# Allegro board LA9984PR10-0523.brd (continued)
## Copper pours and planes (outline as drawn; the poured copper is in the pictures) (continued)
GND on GND1: outline of 173 points within 0.25,0.25 237.15,192.85
GND on GND2: outline of 289 points within 0.26,0.26 237.14,192.84
GNDA on VCC (solid shape): outline of 1322 points within 1.02,7.52 43.27,31.94
GNDA on GND2 (solid shape): outline of 1489 points within 0.26,6.76 43.27,31.94
GNDA on GND1: 0.25,6.75 0.25,10.59 12.58,10.59 12.58,18.93 0.25,18.93 0.25,21.13 11.12,21.13 13.05,23.06 13.05,25.98 13.79,26.72 19.63,26.72 20.84,27.93 21.91,27.93 22.88,28.9 29.28,28.9 29.79,29.4 32.39,29.4 33.09,30.1 34.23,30.1 36.08,31.94 43.27,31.94 43.27,27.69 41.83,27.69 41.52,27.37 37.01,27.37 36.8,27.16 36.8,23.92 36.75,23.88 32.69,23.88 32.22,23.41 32.22,21.42 32.69,20.96 37.22,20.96 37.62,21.36 37.62,22.31 37.66,22.35 38.32,22.35 38.32,20.55 37.43,19.67 37.43,17.68 38.34,16.77 39.36,16.77 39.59,16.53 39.59,14.84 39.48,14.73 21.07,14.73 18.57,12.24 18.57,9.88 17.84,9.45 17.55,8.65 17.55,6.75
VCC on TOP (solid shape): 166.72,170.49 166.72,170.36 166.65,170.3 166.21,170.3 165.38,169.47 165.38,167.18 165.26,167.06 163.73,167.06 163.6,167.18 163.6,169.53 163.67,169.6 164.81,169.6 165.83,170.61 166.59,170.61
VIN on TOP (solid shape): 132.23,178.24 132.74,178.24 134.33,176.66 134.33,176.14 137.38,173.09 139.45,173.09 139.64,172.9 139.64,170.59 139.22,170.17 137.44,170.17 136.81,170.8 136.81,172.58 136.36,173.03 134.9,173.03 133.95,172.07 133.95,170.82 133.44,170.31 131.73,170.31 131.65,170.4 131.65,170.85 131.75,170.95 132.66,170.95 133.07,171.36 133.07,175.98 132.24,176.82 130.52,176.82 130.43,176.91 130.43,178.82 130.15,179.1 129.52,179.1 129.47,179.16 129.47,179.78 129.51,179.83 130.65,179.83
VIN on BOTTOM (solid shape): 142.33,173.03 142.33,172.2 142.71,171.82 143.54,171.82 143.86,171.5 143.86,170.74 143.6,170.49 142.52,170.49 141.7,169.66 139.09,169.66 138.9,169.85 138.9,172.65 139.79,173.53 141.82,173.53
+CHGRTC on BOTTOM (solid shape): 113.69,14.8 113.69,13.53 113.57,13.4 112.68,13.4 111.79,14.29 111.79,14.93 111.98,15.12 113.38,15.12
+CPU_CORE on TOP (solid shape): outline of 2868 points within 93.43,112.83 116.08,145.68
+CPU_CORE on BOTTOM (solid shape): outline of 751 points within 94.14,133.15 113.88,144.83
+CPU_CORE on BOTTOM (solid shape): outline of 1928 points within 94.62,112.68 117.56,125.72
+CPU_CORE on IN1 (solid shape): outline of 295 points within 95.02,115.37 115.85,123.76
+CPU_CORE on IN1 (solid shape): outline of 535 points within 94.01,137.47 111.47,145.02
+CPU_CORE on IN2 (solid shape): outline of 3879 points within 90.52,113.4 115.99,145.34
+CPU_CORE on IN3 (solid shape): outline of 4456 points within 90.52,113.4 115.99,145.34
+CPU_CORE on VCC: outline of 298 points within 88.36,112.13 116.42,144.97
+DIMM1_VREF_DQ on TOP (solid shape): 42.69,76.98 42.69,74.5 42.55,74.37 40.86,74.37 40.42,74.81 40.42,75.63 41.82,77.03 42.64,77.03
+DIMM1_VREF_DQ on BOTTOM (solid shape): 42,75.59 42,72.42 41.94,72.35 40.29,72.35 40.22,72.42 40.22,75.72 40.35,75.85 41.75,75.85
+DIMM2_VREF_DQ on TOP (solid shape): 120.71,75.78 120.71,72.41 120.42,72.12 119.03,72.12 118.65,72.51 118.65,75.68 118.84,75.87 120.62,75.87
+DIMM2_VREF_DQ on BOTTOM (solid shape): 120.55,75.55 120.55,72.38 120.49,72.32 118.84,72.32 118.77,72.38 118.77,75.68 118.9,75.81 120.3,75.81
+DPAB_VDD10 on TOP (solid shape): 169.27,110.33 169.27,108.75 168.93,108.41 168.55,108.41 168.34,108.62 168.34,110.44 168.51,110.6 169,110.6
+DPAB_VDD18 on TOP (solid shape): 175.47,110.92 175.47,109.44 175.01,108.98 175.01,107.64 174.82,107.46 172.8,107.46 172.62,107.28 172.62,107.04 172.62,106.98 172.62,106.89 172.43,106.69 171.98,106.69 171.86,106.82 171.86,107.47 172.57,108.18 173.68,108.18 173.9,108.41 173.9,108.95 173.69,109.15 173.53,109.15 173.31,109.37 173.31,109.65 173.58,109.92 173.87,109.92 174.23,110.28 174.23,111.47 174.28,111.52 174.86,111.52
+DPCD_VDD10 on BOTTOM (solid shape): outline of 159 points within 183.05,100.88 186.36,110.09
+DPCD_VDD18 on BOTTOM (solid shape): outline of 248 points within 176.17,100.84 182.69,110.12
+DPEF_VDD10 on IN1 (solid shape): 169.37,112.91 169.37,112.12 169.3,111.9 169.37,111.68 169.37,111.32 169.09,111.04 168.43,111.04 167.97,111.51 167.97,112.82 168.27,113.13 169.15,113.13
+DPEF_VDD18 on BOTTOM (solid shape): 168.03,116.32 168.03,114.01 167.54,113.52 167.12,113.52 166.89,113.74 166.89,114.52 167.08,114.7 167.08,114.72 167.09,114.73 167.14,114.91 167.08,115.08 167.08,115.21 166.86,115.42 166.86,115.93 167.24,116.3 167.46,116.3 167.52,116.37 167.58,116.41 167.63,116.46 167.65,116.47 167.67,116.47 167.87,116.47
+FAN_POWER on BOTTOM (solid shape): 49.2,111.32 49.2,104.52 49.01,104.34 48.62,104.34 48.4,104.56 48.4,106.68 48.5,106.78 48.5,107.36 48.03,107.82 48.03,111.2 48.32,111.48 49.03,111.48
+INV_PWR_SRC on TOP (solid shape): 231.63,179.42 231.63,178.75 232.05,178.33 233.03,178.33 233.16,178.21 233.16,176.19 232.9,175.93 231.55,175.93 231.36,175.73 229.98,175.73 229.81,175.91 229.81,177.04 230,177.23 230.28,177.23 230.6,177.55 230.6,177.87 230.28,178.18 230,178.18 229.81,178.37 229.81,179.51 230.03,179.73 231.32,179.73
+INV_PWR_SRC on BOTTOM (solid shape): 232.82,177.47 232.82,175.69 232.18,175.06 231.49,175.06 231.36,175.19 231.36,177.53 231.61,177.79 232.5,177.79
+LAN_IO on TOP (solid shape): outline of 199 points within 34.29,83.41 45.12,87.74
+LAN_IO on BOTTOM (solid shape): 51.72,89.65 51.72,87.68 50.64,86.6 49.11,86.6 48.99,86.73 48.99,87.17 49.05,87.24 49.75,87.24 50.64,88.13 50.64,89.27 49.37,90.54 48.07,90.54 47.75,90.54 45.98,90.54 45.8,90.36 45.8,89.2 45.3,89.2 45.29,89.21 45.26,89.18 45.26,88.74 45.3,88.7 45.81,88.7 45.82,88.68 45.82,88.44 45.79,88.42 45.49,88.42 45.37,88.29 45.37,85.97 45.11,85.71 41.88,85.71 40.8,86.79 39.46,86.79 39.4,86.86 39.4,86.98 39.46,87.05 41.49,87.05 41.62,86.92 42.45,86.92 42.64,87.11 42.64,87.75 42.7,87.81 44.16,87.81 44.42,88.07 44.42,90.79 45.3,91.68 49.69,91.68
+LAN_VDD on BOTTOM (solid shape): 34.78,92.21 36.15,92.21 36.3,92.06 36.3,90.71 36,90.41 36,89.6 36.12,89.48 36.12,89.3 36.01,89.19 34.05,89.19 33.83,89.41 33.83,92.46 33.91,92.54 34.46,92.54
+LAN_VDD on IN2 (solid shape): 36.29,90.79 36.29,89.65 36.16,89.52 35.46,89.52 35.27,89.71 35.27,90.67 35.53,90.92 36.16,90.92
+LAN_VDD on IN2 (solid shape): 36.35,85.52 36.35,84.51 36.16,84.32 35.72,84.32 35.27,84.76 35.27,85.59 35.46,85.78 36.1,85.78
+LCDVDD on TOP (solid shape): 220.5,172.93 220.5,171.58 220.18,171.26 219.17,171.26 219.04,171.39 219.04,171.58 219.17,171.71 219.17,171.96 218.79,172.34 217.9,172.34 217.77,172.47 217.77,172.98 217.85,173.05 220.37,173.05
+LCDVDD on BOTTOM (solid shape): 221.2,172.53 221.2,170.31 221.01,170.12 219.61,170.12 219.36,170.37 218.72,170.37 218.6,170.5 218.6,172.47 219.04,172.91 220.82,172.91
+LCDVDD_CONN on BOTTOM (solid shape): 224.69,176.26 224.69,174.61 225.2,174.11 225.2,173.23 225.01,173.04 219.61,173.04 219.55,173.1 219.55,173.99 219.64,174.09 223.25,174.09 223.43,174.26 223.95,174.79 223.95,175.71 223.93,175.85 223.87,175.96 223.87,176.33 223.93,176.39 224.56,176.39
+PCIE_VDDR on TOP (solid shape): 156.63,116.32 156.63,116.02 157.86,114.79 157.86,114.32 157.72,114.18 153.1,114.18 152.91,114.37 152.91,115.37 153.11,115.58 153.75,115.58 153.98,115.81 153.98,116.45 154.04,116.52 156.43,116.52
+PCIE_VDDR on BOTTOM (solid shape): 171.19,122.68 171.19,121.66 171.15,121.62 171.11,121.6 171.08,121.61 170.61,121.59 170.52,121.12 170.53,121.1 170.31,120.87 170.37,120.55 170.37,119.77 170.34,119.73 170.32,119.69 169.97,119.34 168.04,119.34 167.96,119.38 167.94,119.46 167.83,119.73 167.53,119.75 167.52,119.74 167.49,119.75 167.46,119.78 167.46,119.98 167.53,120.19 167.46,120.4 167.46,120.69 167.73,120.96 168.26,120.96 168.5,120.72 168.5,120.7 168.72,120.44 169.05,120.46 169.28,120.46 169.42,120.38 169.59,120.36 169.97,120.58 169.86,121.02 169.85,121.04 169.84,121.06 169.84,121.47 169.85,121.49 169.86,121.51 169.98,121.73 169.93,121.98 169.92,121.99 169.93,122.03 170.01,122.1 170.02,122.12 170.04,122.12 170.33,122.23 170.44,122.52 170.63,122.73 170.79,122.73 170.92,122.78 170.93,122.79 171.08,122.79
+PCIE_VDDR on IN2 (solid shape): outline of 524 points within 155.07,114.97 170.72,123.56
+RTCVCC on BOTTOM (solid shape): 138.9,99.44 138.9,94.98 138.75,94.83 137.89,94.83 137.7,95.02 137.7,98.54 137.32,98.92 133.76,98.92 133.57,99.11 131.98,99.11 131.98,99.75 132.17,99.94 133.32,99.94 133.63,100.26 133.63,100.99 133.76,101.11 137.23,101.11
+SWR_V12 on TOP (solid shape): 200.95,166.75 200.95,163.58 200.75,163.39 199.51,163.39 199.47,163.43 199.47,164.72 199.36,164.84 198.2,164.84 198.12,164.91 198.12,165.75 198.2,165.83 199.65,165.83 199.9,166.08 199.9,166.72 200,166.82 200.88,166.82
+SWR_V12 on IN1 (solid shape): outline of 336 points within 199.71,164.73 206.33,177.75
+VCHGR on TOP (solid shape): 147.16,185.73 147.16,181.09 146.84,180.77 145.76,180.77 143.09,183.44 143.09,184.39 143.48,184.77 145.06,184.77 145.57,185.28 145.76,185.28 146.33,185.85 147.03,185.85
+VCHGR on BOTTOM (solid shape): 145.95,184.96 145.95,184.27 146.27,183.95 148.17,183.95 148.43,183.69 148.43,180.46 148.3,180.33 145.63,180.33 145.13,180.84 145.13,181.47 145,181.6 144.24,181.6 144.17,181.66 144.17,183.31 143.98,183.5 143.54,183.5 143.22,183.19 143.22,181.66 142.97,181.41 142.46,181.41 142.33,181.54 142.33,184.33 142.74,184.74 145.03,184.74 145.44,185.15 145.76,185.15
+VCHGR on IN1 (solid shape): 147.16,185.73 147.16,181.09 146.84,180.77 145.76,180.77 143.09,183.44 143.09,184.39 143.48,184.77 145.06,184.77 145.57,185.28 145.76,185.28 146.33,185.85 147.03,185.85
+VCHGR on IN2 (solid shape): 147.16,185.73 147.16,181.09 146.84,180.77 145.76,180.77 143.09,183.44 143.09,184.39 143.48,184.77 145.06,184.77 145.57,185.28 145.76,185.28 146.33,185.85 147.03,185.85
+VCHGR on IN3 (solid shape): 147.16,185.73 147.16,181.09 146.84,180.77 145.76,180.77 143.09,183.44 143.09,184.39 143.48,184.77 145.06,184.77 145.57,185.28 145.76,185.28 146.33,185.85 147.03,185.85
+VDISPLAY_VCC on BOTTOM (solid shape): 15.71,111.11 15.71,109.15 15.59,109.02 13.3,109.02 12.98,109.34 12.98,111.58 13.34,111.94 14.89,111.94
+VDISPLAY_VCC on IN3 (solid shape): 13.62,111.49 13.62,109.9 12.97,109.25 9.39,109.25 9.17,109.46 9.17,110.99 9.87,111.69 13.43,111.69
+VGA_CORE on TOP (solid shape): 163.48,135.3 163.48,130.04 164.24,129.27 164.24,127.88 163.83,127.46 161.22,127.46 160.49,128.19 159.28,128.19 159,128.47 159,136.16 159.35,136.51 162.27,136.51
+VGA_CORE on TOP (solid shape): 200.78,91.09 209.98,91.09 210.47,90.6 210.47,85.02 209.64,84.19 195.48,84.19 194.4,83.11 189.77,83.11 188.94,83.94 188.94,90.83 189.96,91.84 200.02,91.84
+VGA_CORE on TOP (solid shape): outline of 1056 points within 171.87,114.13 183.13,126.73
+VGA_CORE on BOTTOM (solid shape): 201.59,91.22 212.94,91.22 213.2,90.97 213.2,88.08 213.13,88.01 210.93,88.01 210.92,88.01 210.27,88.01 209.07,86.81 209.07,86.16 206.97,84.06 189.51,84.06 188.94,84.63 188.94,89.14 191.35,91.56 201.26,91.56
+VGA_CORE on IN1 (solid shape): outline of 3193 points within 158.28,113.9 183.65,133.52
+VGA_CORE on VCC (solid shape): outline of 8879 points within 171.8,79.87 209.83,124
+VGA_CORE on IN2 (solid shape): outline of 11817 points within 174.72,84.49 210.86,128.75
+VGA_CORE on IN3 (solid shape): 201.26,91.24 209.77,91.24 211.1,89.9 211.1,84.76 210.28,83.94 189.97,83.94 189,84.9 189,90.22 191.23,92.44 200.05,92.44
+VGA_CORE on IN3 (solid shape): outline of 1021 points within 172.62,115.02 183.77,126.4
+VGA_PCIE on TOP (solid shape): 197.35,80.19 197.35,78.31 197.07,78.03 194.59,78.03 194.34,77.78 192.88,77.78 192.75,77.9 192.75,80.41 192.94,80.6 196.94,80.6
+VGA_PCIE on BOTTOM (solid shape): outline of 123 points within 169.81,123.29 172.91,132.13
+VGA_PCIE on IN2 (solid shape): outline of 3382 points within 169.83,77.01 195.16,131.05
+VGA_PCIE on IN3 (solid shape): outline of 286 points within 161.86,123.41 172.2,127.12
+VGA_PCIEP on TOP (solid shape): 194.97,77.33 195.04,77.27 196.43,77.27 196.5,77.33 196.5,77.76 196.56,77.83 199.8,77.83 200.06,77.56 200.06,74.61 199.8,74.35 193.07,74.35 192.85,74.57 192.85,77.37 193.07,77.59 194.48,77.59 194.72,77.83 194.97,77.83
+VGA_PCIEP on BOTTOM (solid shape): 198.91,77.4 198.91,75.11 198.91,75.11 198.91,74.47 198.78,74.35 193.2,74.35 193.01,74.54 193.01,77.08 193.51,77.59 198.72,77.59
ADPIN on TOP (solid shape): 139.75,179.89 139.75,173.99 139.49,173.73 137.38,173.73 137.09,174.02 137.09,179.86 137.24,180.01 139.63,180.01
ADPIN on BOTTOM (solid shape): 141.19,182.04 141.19,176.26 141.19,176.26 141.19,175.25 138.64,172.71 138.64,172.41 138.19,171.95 135.87,171.95 135.62,172.2 135.62,175.08 136.11,175.57 137.76,175.57 138.33,176.14 138.33,179.76 138.71,180.14 138.71,181.41 139.6,182.3 140.94,182.3
ADPIN on IN3 (solid shape): 140.87,180.46 140.87,173.34 140.62,173.09 136.81,173.09 136.36,173.53 136.36,180.07 136.93,180.65 140.68,180.65
B+ on TOP (solid shape): 136.87,163.37 136.87,158.8 136.55,158.48 134.33,158.48 133.76,159.06 133.76,163.69 134.08,164.01 136.24,164.01
B+ on TOP (solid shape): 229.07,130.93 229.07,128.16 228.53,127.62 225.04,127.62 224.82,127.84 224.82,130.93 225.07,131.18 228.82,131.18
B+ on TOP (solid shape): 176.24,182.93 176.24,181.09 175.99,180.84 166.34,180.84 165.95,181.22 165.95,182.04 165.96,182.05 165.96,182.76 166.58,183.38 175.8,183.38
B+ on TOP (solid shape): 146.52,178.87 146.52,174.68 144.3,172.45 144.3,170.3 143.98,169.98 140.62,169.98 140.17,170.42 140.17,177.22 140.21,177.25 140.21,178.46 140.94,179.19 146.21,179.19
B+ on TOP (solid shape): 228.3,178.75 228.3,178.18 229.39,177.09 229.39,175.82 229.33,175.76 229.01,175.76 228.21,176.56 228.21,177.12 227.59,177.74 226.76,177.74 226.59,177.9 226.59,178.11 226.81,178.33 226.81,178.76 226.92,178.87 228.19,178.87
B+ on TOP (solid shape): 224.63,102.54 224.63,92.13 222.28,89.78 221.07,89.78 218.98,87.68 218.98,85.02 216.37,82.41 212.44,82.41 211.74,83.11 211.74,88.38 213.2,89.84 216.56,89.84 220.37,93.65 221.71,93.65 222.22,94.16 222.22,102.51 222.75,103.05 224.12,103.05
B+ on BOTTOM (solid shape): 137.13,162.04 137.13,151.88 137,151.75 133.76,151.75 133.19,152.33 133.19,161.66 133.95,162.42 136.74,162.42
B+ on BOTTOM (solid shape): 168.43,182.31 168.43,180.98 166.46,179.01 164.62,179.01 164.11,179.52 164.11,181.47 165.33,182.69 168.05,182.69
B+ on BOTTOM (solid shape): 224.57,26.15 224.57,19.15 223.95,18.52 221.78,18.52 221.18,19.12 221.18,26.25 221.32,26.38 224.34,26.38
B+ on BOTTOM (solid shape): 170.69,21.77 170.69,21.43 169.57,20.31 169.02,19.75 168.43,19.75 166.95,21.23 164.34,21.23 163.48,22.09 163.48,23.04 164.27,23.83 168.64,23.83
B+ on BOTTOM (solid shape): 196.05,179.59 196.05,173.15 195.74,172.84 192.18,172.84 191.42,173.6 191.42,175.3 192.69,176.57 192.69,179.63 192.88,179.82 195.83,179.82
B+ on BOTTOM (solid shape): 218.89,87.54 219.68,86.75 219.68,83.76 219.36,83.44 217.01,83.44 216.63,83.82 216.63,84.84 214.28,87.19 214.28,87.51 214.79,88.01 214.79,88.97 215.23,89.41 217.02,89.41
B+ on BOTTOM (solid shape): 229.13,135.82 229.13,128.02 228.68,127.57 227.76,127.57 225.68,125.48 223.71,125.48 223.64,125.55 223.64,127.01 223.32,127.32 223.32,135.59 223.87,136.13 228.82,136.13
B+ on BOTTOM (solid shape): 143.28,180.52 143.28,179 143.48,178.8 143.92,178.8 144.24,179.12 144.24,180.58 144.94,180.58 145.57,179.95 147.54,179.95 148.05,179.44 148.05,172.65 147.86,172.45 142.97,172.45 142.71,172.71 142.71,174.11 142.08,174.74 142.08,180.01 142.71,180.65 143.16,180.65
B+ on IN1 (solid shape): 171.03,182.18 171.03,180.91 170.15,180.03 166.72,180.03 165.95,180.79 165.95,182.31 166.34,182.69 170.53,182.69
B+ on IN1 (solid shape): 144.33,178.65 144.33,172.49 143.73,171.88 141.32,171.88 140.68,172.52 140.68,178.49 141.38,179.19 143.79,179.19
B+ on IN1 (solid shape): 219.05,90.91 219.05,89.42 215.74,86.11 214.96,86.11 213.89,87.18 213.89,88.08 217.44,91.63 218.34,91.63
B+ on IN1 (solid shape): 228.95,130.99 228.95,127.43 227.89,126.38 225.81,126.38 224.82,127.37 224.82,127.38 224.22,127.99 224.22,128.37 227.02,131.18 228.76,131.18
B+ on IN1 (solid shape): outline of 367 points within 180.18,176.79 229.07,182.12
B+ on IN2 (solid shape): 170.59,182.37 170.59,180.6 170.08,180.09 166.4,180.09 166.14,180.34 166.14,182.44 166.46,182.76 170.21,182.76
B+ on IN2 (solid shape): 144.33,178.65 144.33,172.49 143.73,171.88 141.32,171.88 140.68,172.52 140.68,178.49 141.38,179.19 143.79,179.19
B+ on IN2 (solid shape): outline of 199 points within 179.54,176.98 194.97,181.1
B+ on IN3 (solid shape): 169.93,22.55 169.93,17.77 169.31,17.15 167.15,17.15 166.55,17.75 166.55,22.88 166.91,23.24 169.24,23.24
B+ on IN3 (solid shape): 224.35,23.95 224.35,19.18 223.73,18.55 221.57,18.55 220.97,19.15 220.97,24.28 221.33,24.65 223.66,24.65
B+ on IN3 (solid shape): 146.21,179.12 146.21,174.68 144.05,172.52 142.84,172.52 142.08,173.28 142.08,179 142.84,179.76 145.57,179.76
B+ on IN3 (solid shape): 168.88,182.37 168.88,180.27 168.3,179.69 163.6,179.69 163.03,180.27 163.03,181.98 163.48,182.42 166.02,182.42 166.29,182.69 168.56,182.69
B+_1.05V on BOTTOM (solid shape): 141.96,161.15 141.96,159.81 142.21,159.56 143.8,159.56 143.93,159.43 143.93,158.84 144.61,158.16 144.61,157.24 142.55,157.24 142.55,157.25 142.01,156.71 138.4,156.71 137.82,157.28 137.82,161.91 138.14,162.23 140.87,162.23
B+_VDDCI on BOTTOM (solid shape): 192.06,181.45 192.65,181.45 192.78,181.32 192.78,180.85 192.09,180.16 192.09,176.39 191.77,176.07 191.13,176.07 190.91,176.29 190.91,177.02 190.62,177.31 188.46,177.31 188.29,177.47 188.29,179.18 187.77,179.7 187.77,180.63 187.84,180.71 189.93,180.71 190.18,180.96 190.18,181.4 190.61,181.83 191.68,181.83
BATT+ on BOTTOM (solid shape): 154.4,183.88 156.75,183.88 157.13,183.5 158.21,183.5 158.4,183.31 158.4,182.17 157,180.77 155.54,180.77 154.97,180.2 151.41,180.2 151.03,180.58 151.03,184.9 151.29,185.15 153.13,185.15
BATT++ on BOTTOM (solid shape): 173.86,191.08 173.86,186.83 172.43,185.4 158.66,185.4 158.46,185.2 158.46,183.88 158.4,183.82 157.32,183.82 156.49,184.65 154.89,184.65 154.75,184.79 154.75,188.18 155.04,188.47 161.9,188.47 162.21,188.77 169.5,188.77 169.96,189.23 169.96,191 170.45,191.49 173.45,191.49
BATT++ on IN2 (solid shape): 173.86,191.08 173.86,186.83 172.43,185.4 157.34,185.4 156.68,186.06 156.68,188.02 157.13,188.47 161.9,188.47 162.21,188.77 169.5,188.77 169.96,189.23 169.96,191 170.45,191.49 173.45,191.49
BATT++ on IN3 (solid shape): 173.86,191.08 173.86,186.83 172.43,185.4 157.28,185.4 156.68,185.99 156.68,187.96 157.19,188.47 161.9,188.47 162.21,188.77 169.5,188.77 169.96,189.23 169.96,191 170.45,191.49 173.45,191.49
BOOT_1.35V on BOTTOM (solid shape): 157.38,26.91 157.38,26.8 157.32,26.73 155.99,26.73 155.29,26.04 154.4,26.04 154.33,26.11 154.33,26.73 154.4,26.8 155.67,26.8 155.86,26.99 157.31,26.99
BST on TOP (solid shape): 165.64,172.07 166.72,172.07 166.78,172.01 166.78,171.88 166.72,171.82 165.57,171.82 165.45,171.69 164.43,171.69 164.3,171.57 164.3,171.12 164.24,171.06 163.6,171.06 163.54,171.12 163.54,172.07 163.73,172.26 165.45,172.26
BST_1.05V on BOTTOM (solid shape): 147.37,159.24 147.37,158.44 147.35,158.41 146.59,158.41 146.21,158.03 146.21,158.02 145.96,157.77 145.41,157.77 145.34,157.84 145.34,158.32 145.44,158.43 145.91,158.43 146.4,158.92 146.4,159.17 146.53,159.3 147.31,159.3
BST_1.35V on BOTTOM (solid shape): 155.36,25.27 155.36,23.3 155.29,23.23 154.4,23.23 154.34,23.29 154.34,25.27 154.4,25.34 155.29,25.34
BST_+1.2VSP on TOP (solid shape): 185.7,173.34 185.7,173.22 185.48,172.99 185.48,170.77 185.39,170.68 184.81,170.68 184.75,170.74 184.75,173.22 184.94,173.41 185.64,173.41
BST_CHGA on TOP (solid shape): 163.03,173.41 163.03,170.04 162.84,169.85 162.14,169.85 162.08,169.91 162.08,173.47 162.14,173.53 162.91,173.53
BST_VGA_CORE on BOTTOM (solid shape): 201.9,62.35 201.9,62.28 203.32,60.85 203.77,60.85 203.93,60.69 203.93,60.57 203.86,60.5 202.97,60.5 202.88,60.6 202.88,60.73 202.56,61.04 202.18,61.04 201.7,61.52 201.13,61.52 200.88,61.77 200.88,62.41 200.94,62.47 201.77,62.47
CHG_B+ on TOP (solid shape): 158.21,171.12 158.21,164.01 157.64,163.44 146.8,163.44 145.36,164.89 145.36,169.79 145.48,169.91 156.68,169.91 157.25,170.49 157.25,170.93 157.57,171.25 158.08,171.25
CHG_B+ on BOTTOM (solid shape): 158.72,166.68 158.72,164.39 157.76,163.44 149.44,163.44 148.81,164.07 148.81,166.87 149.19,167.25 158.14,167.25
DH_1.35V on TOP (solid shape): 154.02,21.53 154.02,20.32 153.83,20.13 153.07,20.13 152.82,20.38 152.82,21.72 152.94,21.85 153.71,21.85
DH_1.35V on TOP (solid shape): 156.37,26.35 156.37,26.1 155.17,24.89 154.85,24.89 154.34,25.4 154.34,25.66 155.23,26.54 156.18,26.54
DH_1.35V on BOTTOM (solid shape): 155.23,20.64 155.23,20.26 155.04,20.07 153.01,20.07 152.82,20.26 152.82,20.58 153.07,20.83 155.04,20.83
DH_1.35V on BOTTOM (solid shape): 156.61,26.61 157.32,26.61 157.39,26.54 157.39,26.4 157.34,26.35 156.56,26.35 155.99,25.78 155.99,25.66 155.86,25.53 155.61,25.53 155.48,25.66 155.48,25.97 156.12,26.61 156.6,26.61
DH_CHG on TOP (solid shape): 152.49,171.76 152.49,170.8 152.36,170.68 151.34,170.68 151.24,170.78 151.24,171.82 151.37,171.95 152.3,171.95
DH_CHG on TOP (solid shape): 166.78,171.44 166.78,171.38 166.72,171.31 165.76,171.31 165.57,171.12 164.56,171.12 164.49,171.18 164.49,171.5 164.56,171.57 166.65,171.57
DH_CHG on TOP (solid shape): 146.15,171.81 146.15,170.67 146.04,170.55 145.5,170.55 145.5,170.55 144.84,170.55 144.78,170.61 144.78,171.86 144.87,171.95 146.01,171.95
DH_CHG on IN1 (solid shape): 153.13,171.69 153.13,170.87 152.94,170.68 150.27,170.68 150.08,170.87 150.08,171.63 150.33,171.88 152.94,171.88
DH_CHG on IN1 (solid shape): 146.28,171.63 146.28,170.71 146.22,170.65 145.01,170.65 144.92,170.75 144.92,171.63 145.04,171.76 146.15,171.76
DH_CHG on IN1 (solid shape): 164.49,171.69 165.26,171.69 165.51,171.44 165.51,171.18 165.38,171.06 163.67,171.06 163.35,171.38 163.35,172.01 163.48,172.14 164.05,172.14
DL_1.35V on BOTTOM (solid shape): 157.58,14.73 157.58,13.84 157.45,13.72 156.56,13.72 156.44,13.84 156.44,14.67 156.56,14.8 157.52,14.8
DL_1.35V on BOTTOM (solid shape): 157.83,25.71 157.83,24.77 157.71,24.64 157.71,22.86 157.51,22.66 157.21,22.66 157.09,22.78 157.09,24.47 157.58,24.96 157.58,25.71 157.64,25.77 157.77,25.77
DL_1.35V on IN3 (solid shape): 157.58,14.99 157.58,13.78 157.48,13.68 156.53,13.68 156.44,13.78 156.44,15.05 156.63,15.24 157.32,15.24
DL_1.35V on IN3 (solid shape): 157.71,24.58 157.71,23.62 158.02,23.31 158.02,21.72 157.9,21.59 157.2,21.59 156.94,21.85 156.94,23.37 157.2,23.62 157.2,24.51 157.39,24.7 157.58,24.7
DL_CHG on TOP (solid shape): 161.83,177.53 161.83,176.9 161.57,176.65 160.18,176.65 159.99,176.46 159.16,176.46 158.97,176.65 158.97,177.47 159.16,177.66 161.7,177.66
DL_CHG on TOP (solid shape): 166.72,175.25 166.72,173.98 167.1,173.6 167.1,172.71 167.03,172.65 166.91,172.65 166.84,172.71 166.84,172.77 165.64,173.98 165.64,175.19 165.95,175.5 166.46,175.5
EN_PCIE on BOTTOM (solid shape): 197.23,68.31 197.23,67.76 197.48,67.51 198.16,67.51 198.26,67.41 198.26,66.77 198.17,66.68 196.55,66.68 196.16,67.08 195.57,67.08 195.51,67.14 195.51,68.24 195.67,68.4 197.15,68.4
ERP_LOT6 on TOP (solid shape): 129.07,176.16 129.07,174.91 129.88,174.1 130.43,173.55 130.62,173.55 130.7,173.47 130.7,173.04 130.38,172.72 129.67,172.72 128.85,173.54 128.09,173.54 127.92,173.71 126.03,173.71 125.94,173.8 125.94,174.37 126.04,174.48 128.46,174.48 128.67,174.69 128.67,176.18 128.76,176.27 128.97,176.27
GPU_B+ on TOP (solid shape): 216.06,79.87 216.06,78.16 214.57,76.67 214.06,76.67 213.64,76.25 213.64,65.34 212.63,64.33 210.47,64.33 210.21,64.58 209.26,64.58 208.5,63.82 208.12,63.82 207.36,64.58 207.1,64.58 206.91,64.77 206.91,78.03 208.25,79.36 210.34,79.36 211.17,80.19 215.74,80.19
INT-SPK-L+ on TOP (solid shape): 39.34,20.26 39.34,19.94 38.64,19.24 38.38,19.24 38.19,19.43 38.19,19.88 38.76,20.45 39.14,20.45
INT-SPK-L+ on TOP (solid shape): 61.56,37.33 61.56,36.56 61.43,36.44 58.7,36.44 58.58,36.56 58.58,37.26 58.77,37.45 61.43,37.45
INT-SPK-L+ on IN1 (solid shape): 60.73,37.15 60.73,36.56 60.61,36.44 57.88,36.44 57.75,36.56 57.75,37.15 57.81,37.21 60.67,37.21
INT-SPK-L+ on IN1 (solid shape): 40.55,21.34 40.55,20.83 40.28,20.56 40.27,20.56 38.89,19.18 38.56,19.18 38.3,19.43 38.3,19.7 40.07,21.47 40.42,21.47
INT-SPK-L- on TOP (solid shape): 61.56,36.12 61.56,35.29 61.5,35.23 58.83,35.23 58.58,35.49 58.58,36.06 58.83,36.31 61.37,36.31
INT-SPK-L- on TOP (solid shape): 39.78,20.01 39.78,18.93 39.34,18.48 39.08,18.48 38.89,18.67 38.89,19.1 39.46,19.67 39.46,19.74 39.53,19.8 39.53,20.01 39.59,20.07 39.72,20.07
INT-SPK-L- on IN1 (solid shape): 60.73,35.88 60.73,35.44 60.61,35.31 57.81,35.31 57.75,35.37 57.75,35.94 57.88,36.07 60.54,36.07
INT-SPK-L- on IN1 (solid shape): 40.8,19.88 40.8,19.56 39.53,18.3 39.15,18.3 38.81,18.64 38.81,18.84 39.37,19.4 39.56,19.4 40.32,20.16 40.51,20.16
INT-SPK-R+ on TOP (solid shape): 41.68,19.43 41.68,17.23 41.56,17.1 40.91,17.1 40.86,17.15 40.86,19.55 40.99,19.67 41.44,19.67
INT-SPK-R+ on TOP (solid shape): 62.51,34.41 62.51,33.58 62.45,33.52 60.1,33.52 59.91,33.71 59.91,34.34 60.1,34.53 62.39,34.53
INT-SPK-R+ on IN1 (solid shape): 61.69,34.29 61.69,33.78 61.56,33.66 59.13,33.66 59.08,33.71 59.08,34.34 59.16,34.42 61.56,34.42
INT-SPK-R+ on IN1 (solid shape): 41.68,18.99 42.71,18.99 42.84,18.86 42.84,18.42 42.64,18.22 41.62,18.22 41.56,18.16 41.23,18.16 41.04,18.35 41.04,19.12 41.15,19.23 41.43,19.23
INT-SPK-R- on TOP (solid shape): 40.67,19.42 40.67,17.28 40.48,17.1 40.09,17.1 40.03,17.15 40.03,19.48 40.22,19.67 40.41,19.67
INT-SPK-R- on TOP (solid shape): 62.51,33.14 62.51,32.31 62.45,32.25 59.97,32.25 59.85,32.37 59.85,33.14 59.97,33.26 62.39,33.26
INT-SPK-R- on IN1 (solid shape): 61.47,32.98 61.47,32.55 61.37,32.45 59.21,32.45 59.02,32.64 59.02,33.14 59.15,33.26 61.18,33.26
INT-SPK-R- on IN1 (solid shape): 40.71,17.89 41.33,17.89 41.43,17.78 41.43,17.21 41.3,17.08 40.16,17.08 40.03,17.21 40.03,18.07 40.14,18.18 40.41,18.18
KB_BL_PWM on TOP (solid shape): 41.85,118.36 41.85,117.15 41.73,117.03 40.14,117.03 40.04,117.13 40.04,118.34 40.14,118.44 41.77,118.44
KB_BL_PWM on BOTTOM (solid shape): 43.88,118.14 43.88,116.04 43.65,115.82 40.03,115.82 39.81,116.04 39.81,118.21 39.97,118.36 43.65,118.36
LDO_3V on BOTTOM (solid shape): 147.35,157.21 146.69,157.21 146.64,157.26 146.01,157.26 145.96,157.31 145.39,157.31 145.34,157.36 145.34,157.51 145.39,157.56 146,157.56 146.21,157.78 146.38,157.78 146.69,158.1 147.35,158.1
LG_3V on TOP (solid shape): 216.06,17.59 216.06,16.96 215.87,16.77 214.6,16.77 214.44,16.93 214.44,17.43 214.6,17.59 215.29,17.59 215.48,17.78 215.87,17.78
LG_3V on TOP (solid shape): 210.57,18.48 210.57,18.18 210.45,18.05 210.15,18.05 209.79,18.4 209.79,18.41 208.9,19.31 208.3,19.31 208.25,19.36 208.25,19.48 208.29,19.53 209.53,19.53
LG_3V on BOTTOM (solid shape): 216.06,17.72 216.06,16.89 215.87,16.7 215.23,16.7 215.04,16.89 215.04,17.78 215.1,17.85 215.93,17.85
LG_5V on TOP (solid shape): 210.12,22.32 210.12,22.04 210.11,22.02 210.1,22 210.06,21.96 210.02,21.9 209.26,21.14 209.26,21.03 209.15,20.92 208.3,20.92 208.24,20.98 208.24,21.09 208.3,21.15 208.64,21.15 209.04,21.54 209.04,21.87 209.58,22.42 210.01,22.42
LG_5V on BOTTOM (solid shape): 213.52,24.64 213.52,23.88 213.39,23.75 212.63,23.75 212.44,23.94 212.44,24.77 212.56,24.89 213.26,24.89
LG_5V on IN3 (solid shape): 210.73,22.68 209.47,21.42 209.06,21.42 208.93,21.56 208.93,21.85 210.13,23.06 210.35,23.06
LG_5V on IN3 (solid shape): 212.92,24.7 212.92,23.88 212.81,23.76 212,23.76 211.99,23.75 211.58,23.75 211.3,24.04 211.3,24.25 211.87,24.83 212.8,24.83
LG_+1.2VSP on BOTTOM (solid shape): 180.88,174.91 180.88,174.11 180.69,173.92 179.8,173.92 179.67,174.04 179.67,175.04 179.77,175.14 180.64,175.14
LG_+1.2VSP on IN3 (solid shape): 180.81,174.99 180.81,174.04 180.69,173.92 179.92,173.92 179.73,174.11 179.73,174.93 179.86,175.06 180.75,175.06
LG_+1.2VSP on IN3 (solid shape): 185.83,176.33 185.83,175.69 185.7,175.57 184.81,175.57 184.69,175.69 184.69,176.71 184.81,176.84 185.32,176.84
LX_1.05V on BOTTOM (solid shape): 147.67,161.02 147.67,159.91 147.38,159.62 146.66,159.62 146.53,159.75 146.53,161.02 146.66,161.14 147.55,161.14
LX_1.05V on BOTTOM (solid shape): 144.59,154.95 144.99,154.54 145.32,154.54 145.89,153.97 145.89,150.03 145.39,149.52 142.32,149.52 140.74,147.94 138.85,147.94 138.72,148.07 138.72,149.03 139.09,149.4 139.79,149.4 141.07,150.68 141.07,152.63 143.42,154.98 143.42,156.18 144.59,156.18
LX_1.5VSP on BOTTOM (solid shape): 108.87,23.4 108.87,20.47 108.62,20.22 108.15,20.22 107.88,19.95 107.88,18.92 107.88,18.92 107.88,18.22 107.81,18.15 107.7,18.15 107.62,18.23 107.62,18.95 107.48,19.09 107.07,19.09 106.59,18.62 105.93,18.62 105.87,18.68 105.87,19.64 105.7,19.81 104.84,19.81 104.69,19.96 104.69,23.28 104.89,23.48 108.78,23.48
LX_1.8VSP on BOTTOM (solid shape): 221.58,97.21 221.58,96.06 221.39,95.87 219.93,95.87 219.17,95.11 219.17,94.1 219.04,93.97 218.98,93.97 218.91,94.03 218.91,95.05 218.09,95.87 217.26,95.87 216.5,96.64 215.67,96.64 215.61,96.7 215.61,97.4 215.67,97.46 221.33,97.46
LX_3V on TOP (solid shape): 207.25,19.09 207.25,18.1 207.44,17.91 207.44,17.02 207.31,16.89 207.31,16.39 207.12,16.2 206.61,16.2 206.55,16.26 206.55,16.83 206.93,17.21 206.93,18.04 207.05,18.16 207.05,19.08 207.08,19.12 207.22,19.12
LX_3V on BOTTOM (solid shape): 215.74,15.88 215.74,14.1 216.12,13.72 217.26,13.72 217.45,13.91 217.45,14.93 217.64,15.12 219.1,15.12 219.68,14.54 219.68,7.37 219.17,6.86 214.53,6.86 214.25,7.14 214.25,12.05 213.71,12.6 210.41,12.6 210.15,12.86 210.15,15.94 210.47,16.26 215.36,16.26
LX_3V on IN1 (solid shape): 210.72,13.78 210.72,13.02 210.53,12.83 210.15,12.83 209.26,13.72 209.26,14.29 209.52,14.54 209.96,14.54
LX_3V on IN1 (solid shape): 207.75,17.69 207.75,16.96 208.04,16.67 208.04,16.39 207.79,16.13 207.5,16.13 206.93,16.7 206.93,17.91 207.05,18.04 207.41,18.04
LX_5V on TOP (solid shape): 207.85,24.2 207.85,22.96 207.28,22.39 207.28,22.29 207.25,22.26 207.25,21.34 207.23,21.32 207.08,21.32 207.04,21.36 207.04,22.5 206.93,22.61 206.93,23.4 207.15,23.62 207.15,24.16 207.28,24.28 207.76,24.28
LX_5V on BOTTOM (solid shape): 220.31,33.47 220.31,29.78 218.79,28.26 218.79,26.67 218.69,26.58 215.73,26.58 215.41,26.25 215.41,25.33 215.36,25.28 211.1,25.28 210.66,25.72 210.66,28.64 211.17,29.15 214.28,29.15 214.91,29.78 214.91,33.66 215.36,34.1 219.68,34.1
LX_5V on IN1 (solid shape): 207.94,24.77 207.94,22.61 207.69,22.35 207.17,22.35 206.91,22.61 206.91,24.58 207.23,24.89 207.82,24.89
LX_5V on IN1 (solid shape): 212.88,27.82 212.88,26.93 212.75,26.8 212.44,26.8 212.25,26.99 211.61,26.99 211.61,27.75 212.25,27.75 212.44,27.94 212.75,27.94
LX_CHG on TOP (solid shape): 166.78,170.99 166.78,170.87 166.72,170.8 165.76,170.8 164.87,169.91 163.6,169.91 163.54,169.98 163.54,170.74 163.6,170.8 164.56,170.8 164.68,170.93 165.57,170.93 165.7,171.06 166.72,171.06
LX_CHG on TOP (solid shape): 155.03,178.89 155.03,177.22 155.1,177.15 157.99,177.15 158.08,177.06 158.08,172.9 158.02,172.84 156.87,172.84 156.43,172.39 156.43,170.87 156.24,170.68 154.33,170.68 154.14,170.49 154.14,170.17 154.02,170.04 153.25,170.04 153.06,170.23 153.06,171.88 152.62,172.33 151.22,172.33 150.84,171.95 150.84,170.8 150.62,170.58 146.92,170.58 146.77,170.73 146.77,172.77 148.9,174.9 149.35,174.9 153.42,178.97 154.95,178.97
LX_CHG on BOTTOM (solid shape): 157.51,176.46 157.51,170.61 156.81,169.91 153.06,169.91 152.75,170.23 152.75,171.76 152.3,172.2 149.06,172.2 148.75,172.52 148.75,174.99 150.52,176.77 157.19,176.77
LX_CHG on IN1 (solid shape): 155.67,170.74 155.67,170.04 155.48,169.85 153.25,169.85 153.06,170.04 153.06,170.55 153.38,170.87 155.54,170.87
LX_CHG on IN1 (solid shape): 165.51,170.8 165.51,170.42 164.94,169.85 163.48,169.85 163.29,170.04 163.29,170.68 163.48,170.87 164.56,170.87 164.62,170.93 165.38,170.93
LX_PCIE on TOP (solid shape): 197.77,71.43 197.77,69.9 197.6,69.73 195.72,69.73 195.41,69.43 195.41,66.95 195.27,66.8 193.09,66.8 193.09,66.8 192.77,67.12 192.77,71.46 192.91,71.6 197.6,71.6
LX_PCIE on BOTTOM (solid shape): 197.85,71.84 197.85,69.07 197.6,68.82 195.53,68.82 194.81,68.09 194.81,67.2 194.72,67.12 193.08,67.12 192.84,67.36 192.84,71.89 193.24,72.3 197.39,72.3
LX_VDDCI on TOP (solid shape): 190.14,186.38 190.14,184.32 189.26,183.44 189.26,182.44 189.13,182.31 188.16,182.31 187.79,182.67 187.79,186.24 187.99,186.44 190.07,186.44
LX_VDDCI on BOTTOM (solid shape): 190.84,189.01 190.84,185.68 189.02,183.86 189.02,181.76 188.96,181.71 187.88,181.71 187.79,181.8 187.79,188.82 188.12,189.15 190.7,189.15
M_ODT on TOP (solid shape): 85.07,59.67 85.07,55.09 84.99,55 84.25,55 84.12,55.13 84.12,56.64 83.58,57.19 82.41,57.19 82.22,57.38 82.22,58.21 82.5,58.49 83.09,58.49 83.53,58.93 83.53,59.57 83.79,59.82 84.93,59.82
MIC_IN on TOP (solid shape): 24.22,25.97 24.22,25.28 24.1,25.15 21.81,25.15 21.75,25.21 21.75,26.23 21.81,26.29 23.9,26.29
MIC_IN on TOP (solid shape): 39.65,29.34 39.65,27.37 39.59,27.31 39.53,27.31 39.46,27.37 39.46,28.32 39.14,28.64 39.14,29.4 39.27,29.53 39.46,29.53
MIC_IN on IN1 (solid shape): 24.79,26.16 24.79,25.4 24.54,25.15 22.76,25.15 22.63,25.28 22.63,26.1 22.83,26.29 24.67,26.29
MIC_IN on IN1 (solid shape): 39.65,29.66 39.65,28.64 39.46,28.45 39.34,28.45 38.76,29.02 37.75,29.02 37.56,29.21 37.56,29.78 37.81,30.04 39.27,30.04
MIC_IN_R on TOP (solid shape): 18.82,25.78 19.97,25.78 20.16,25.97 20.16,26.16 20.29,26.29 21.3,26.29 21.43,26.16 21.43,25.15 21.3,25.02 18.63,25.02 18.51,25.15 17.18,25.15 17.17,25.19 16.92,25.51 16.53,25.42 16.49,25.39 16.16,25.72 16.16,26.29 16.41,26.55 18.06,26.55
PCIE_B+ on BOTTOM (solid shape): 194.85,64.82 194.85,64 195.67,63.17 195.67,60.69 195.56,60.58 193.69,60.58 193.58,60.69 193.58,61.08 194.02,61.52 194.02,63.55 193.51,64.06 193.51,64.89 193.58,64.95 194.72,64.95
PSID on BOTTOM (solid shape): 138.38,185.07 138.38,180.16 138.11,179.9 135.72,179.9 135.36,180.25 135.36,185.2 135.53,185.37 138.08,185.37
REGN on TOP (solid shape): 165.19,174.93 165.19,173.53 166.14,172.58 166.65,172.58 166.78,172.45 166.78,172.39 166.65,172.26 165.76,172.26 165.51,172.52 164.3,172.52 164.18,172.65 164.18,173.47 164.37,173.66 164.37,175.06 164.43,175.12 165,175.12
RING2 on TOP (solid shape): 24.22,24.83 24.22,24.32 23.52,23.62 21.81,23.62 21.75,23.69 21.75,24.7 21.81,24.77 23.46,24.77 23.59,24.89 24.16,24.89
RING2 on TOP (solid shape): 40.35,29.34 40.35,29.21 40.29,29.15 40.29,28.64 40.13,28.48 40.13,28.41 40.03,28.32 40.03,27.37 39.97,27.31 39.91,27.31 39.84,27.37 39.84,29.34 39.97,29.47 40.22,29.47
RING2 on IN3 (solid shape): 25.17,24.58 25.17,23.82 24.92,23.56 23.02,23.56 22.89,23.69 22.89,24.45 23.21,24.77 24.98,24.77
RING2 on IN3 (solid shape): 40.99,30.55 40.99,28.7 40.73,28.45 39.97,28.45 39.84,28.58 39.84,30.55 39.97,30.67 40.86,30.67
RING2_R on TOP (solid shape): 21.36,24.64 21.36,23.69 21.17,23.5 20.48,23.5 19.97,24.01 19.14,24.01 17.75,22.61 16.67,22.61 16.28,22.99 16.28,23.62 16.92,24.26 18.25,24.26 18.76,24.77 21.24,24.77
SNB_1.05V on BOTTOM (solid shape): 139.67,152 139.93,151.75 140.37,151.75 140.37,150.73 138.72,150.73 138.65,150.8 138.65,152.69 138.78,152.82 139.67,152.82
SNB_VDDCI on TOP (solid shape): 189.07,190.31 189.07,189.36 189.39,189.04 190.02,189.04 190.08,188.98 190.08,188.03 190.02,187.96 188.31,187.96 188.12,188.15 188.12,190.25 188.31,190.44 188.94,190.44
SNUB_PCIE on TOP (solid shape): 197.96,68.75 197.96,66.82 197.85,66.71 196.86,66.71 196.78,66.8 196.78,67.51 196.71,67.58 195.96,67.58 195.75,67.78 195.75,68.84 195.87,68.97 197.74,68.97
SW_1.35V on TOP (solid shape): 154.66,18.86 154.66,17.65 154.72,17.59 154.72,17.34 154.59,17.21 153.77,17.21 153.58,17.4 153.58,18.8 153.77,18.99 154.53,18.99
SW_1.35V on TOP (solid shape): 157.39,25.66 157.39,25.4 156.37,24.39 156.05,24.39 155.74,24.7 155.74,25.15 156.44,25.85 157.2,25.85
SW_1.35V on BOTTOM (solid shape): 157.39,26.09 157.39,25.4 156.82,24.83 156.82,23.37 156.56,23.12 156.05,23.12 155.93,23.24 155.93,25.34 156.47,25.88 156.47,26.07 156.56,26.16 157.32,26.16
SW_1.35V on BOTTOM (solid shape): 155.16,19.74 155.16,17.33 155.93,16.56 155.93,13.7 156.05,13.58 156.56,13.58 156.68,13.45 156.68,12.94 156.62,12.88 154.1,12.88 152.37,14.61 150.34,14.61 149.96,14.99 149.96,18.61 150.72,19.37 153.07,19.37 153.5,19.8 153.51,19.8 153.57,19.86 155.03,19.86
SW_+1.2VSP on TOP (solid shape): 176.88,174.74 176.88,173.47 177.07,173.28 177.59,173.28 178.2,173.28 179.42,173.28 179.48,173.22 179.48,172.38 179.38,172.28 179.09,172.28 178.84,172.04 178.84,169.83 178.68,169.66 175.67,169.66 175.1,170.23 175.1,174.68 175.23,174.8 176.81,174.8
SW_+1.2VSP on TOP (solid shape): 185.7,174.36 185.7,174.23 185.64,174.17 184.81,174.17 184.69,174.04 184.44,174.04 184.38,173.98 184.37,173.98 184.12,173.73 183.87,173.73 183.8,173.72 183.67,173.6 183.67,173.41 183.54,173.28 182.72,173.28 182.65,173.34 182.65,173.92 183.16,174.42 185.64,174.42
SW_+1.2VSP on BOTTOM (solid shape): 179.42,177.03 179.42,170.04 179.1,169.72 175.16,169.72 174.78,170.11 174.78,174.23 177.66,174.23 177.67,174.17 177.68,174.12 177.7,174.07 177.73,174.03 177.77,173.97 177.77,173.94 177.77,173.91 177.73,173.85 177.7,173.81 177.68,173.76 177.67,173.71 177.66,173.65 177.67,173.6 177.68,173.55 177.7,173.5 177.72,173.45 177.76,173.41 177.8,173.37 177.84,173.34 177.89,173.32 177.94,173.3 177.99,173.29 178.05,173.29 178.1,173.3 178.15,173.32 178.2,173.34 178.24,173.37 178.28,173.41 178.32,173.45 178.34,173.5 178.36,173.55 178.37,173.6 178.38,173.65 178.37,173.71 178.36,173.76 178.34,173.81 178.31,173.85 178.27,173.91 178.27,173.94 178.27,173.97 178.31,174.03 178.34,174.07 178.36,174.12 178.37,174.17 178.38,174.23 178.37,174.28 178.36,174.33 178.34,174.38 178.32,174.43 178.28,174.47 178.24,174.51 178.2,174.54 178.15,174.56 178.1,174.58 178.05,174.59 177.99,174.59 177.94,174.58 177.89,174.56 177.84,174.54 177.8,174.51 177.76,174.47 177.72,174.43 177.7,174.38 177.68,174.33 177.67,174.28 177.66,174.23 174.78,174.23 174.78,175.99 176.2,177.41 179.04,177.41
SW_+1.2VSP on IN1 (solid shape): 179.73,173.03 180.56,173.03 180.69,172.9 180.69,172.45 180.5,172.26 179.23,172.26 179.04,172.45 179.04,173.15 179.23,173.34 179.42,173.34
SW_+1.2VSP on IN1 (solid shape): 184.75,174.36 184.75,174.11 184.63,173.98 184.6,173.99 184.53,173.99 184.45,173.98 184.13,173.98 183.99,173.98 183.35,173.34 182.91,173.34 182.78,173.47 182.78,173.85 183.42,174.49 184.62,174.49
SW_CPU2 on BOTTOM (solid shape): 112.36,144.97 112.36,142.77 112.32,142.74 110.96,142.74 110.94,142.71 110.78,142.62 110.68,142.45 110.65,142.42 110.65,141.21 110.46,141.02 109.38,141.02 109.19,140.83 109.19,140.2 109.12,140.13 106.26,140.13 106.2,140.2 106.2,141.53 106.39,141.72 108.3,141.72 108.42,141.85 108.42,142.55 108.36,142.61 106.52,142.61 106.14,142.99 106.14,144.83 106.65,145.34 111.99,145.34
SW_VGA_CORE on TOP (solid shape): 206.66,77.71 206.66,76.86 206.4,76.61 206.4,73.5 206.11,73.2 203.8,73.2 203.55,72.95 203.55,71.82 203.99,71.38 206.15,71.38 206.47,71.06 206.47,65.92 206.21,65.66 202.91,65.66 202.09,66.49 202.09,77.9 202.72,78.54 205.83,78.54
SW_VGA_CORE on BOTTOM (solid shape): 204.56,63.87 204.56,62.81 204.49,62.59 204.56,62.37 204.56,62.09 204.69,61.96 204.69,60.89 204.63,60.82 204.56,60.82 204.44,60.95 204.44,61.89 204.44,61.9 204.24,62.09 204.18,62.09 204.05,62.22 204.05,62.91 204.05,63.04 203.86,63.23 203.55,63.23 203.48,63.3 203.48,64.06 203.55,64.12 204.31,64.12
SW_VGA_CORE on BOTTOM (solid shape): outline of 91 points within 202.09,63.74 214.44,80.2
SW_VGA_CORE on IN1 (solid shape): 205.45,64.76 205.45,64.71 205.51,64.65 205.51,64.07 205.26,63.82 204.83,63.82 204.63,63.62 204.63,62.22 204.44,62.03 204.12,62.03 204.05,62.09 204.05,64.19 204.82,64.95 205.26,64.95
SW_VGA_CORE on IN1 (solid shape): 206.85,77.78 206.85,76.63 206.28,76.06 206.28,67.68 206.02,67.43 203.24,67.43 202.85,67.82 202.85,71.06 202.96,71.17 205.2,71.17 205.39,71.36 205.39,72.82 205.07,73.14 202.34,73.14 202.09,73.39 202.09,77.2 203.1,78.22 206.4,78.22
SW_VGA_CORE on IN2 (solid shape): 206.85,77.78 206.85,76.63 206.28,76.06 206.28,67.68 206.02,67.43 203.23,67.43 203.22,67.43 203.05,67.43 202.85,67.63 202.85,71.06 202.96,71.17 205.2,71.17 205.39,71.36 205.39,72.82 205.06,73.15 202.16,73.15 201.96,73.35 201.96,77.08 203.1,78.22 206.4,78.22
SW_VGA_CORE on IN3 (solid shape): 206.85,77.78 206.85,76.63 206.28,76.06 206.28,67.68 206.02,67.43 203.17,67.43 202.85,67.74 202.85,70.92 203.1,71.17 205.2,71.17 205.39,71.36 205.39,72.82 205.07,73.14 202.34,73.14 202.09,73.39 202.09,77.2 203.1,78.22 206.4,78.22
UG_3V on TOP (solid shape): 208.21,19.18 208.64,19.18 209.43,18.39 209.43,18.13 209.15,17.85 208.9,17.85 208.52,18.23 207.9,18.23 207.84,18.29 207.84,19.1 207.91,19.18
UG_3V on BOTTOM (solid shape): 217.26,14.93 217.26,14.1 217.07,13.91 216.37,13.91 216.18,14.1 216.18,14.99 216.31,15.12 217.07,15.12
UG_3V on IN1 (solid shape): 210.17,17.55 210.17,17.39 209.73,16.96 209.61,16.96 208.2,18.37 208.2,18.98 208.34,19.12 208.6,19.12
UG_3V on IN1 (solid shape): 216.6,14.83 216.6,14 216.47,13.88 215.07,13.88 214.88,14.07 214.88,14.7 215.14,14.96 216.47,14.96
UG_5V on TOP (solid shape): 208.79,22.43 208.79,21.55 208.52,21.28 207.98,21.28 207.85,21.4 207.85,22.16 208.29,22.61 208.61,22.61
UG_5V on BOTTOM (solid shape): 220.06,27.43 220.06,26.67 219.87,26.48 219.17,26.48 219.04,26.61 219.04,27.5 219.17,27.63 219.87,27.63
UG_5V on IN1 (solid shape): 208.98,23.17 208.98,22.5 208.77,22.29 208.77,21.4 208.71,21.34 208.39,21.34 208.13,21.59 208.13,23.24 208.3,23.41 208.74,23.41
UG_5V on IN1 (solid shape): 220.12,27.37 220.12,26.61 219.99,26.48 218.91,26.48 218.72,26.67 218.72,27.12 219.1,27.5 219.99,27.5
UG_+1.2VSP on TOP (solid shape): 178.27,174.36 178.27,173.53 178.15,173.41 177.64,173.41 177.13,173.92 177.13,174.61 177.26,174.74 177.89,174.74
UG_+1.2VSP on TOP (solid shape): 185.77,173.85 185.77,173.72 185.64,173.6 184.88,173.6 184.37,173.09 183.99,173.09 183.8,173.28 183.8,173.47 183.92,173.6 184.18,173.6 184.46,173.88 184.48,173.88 184.57,173.88 184.65,173.91 184.66,173.92 185.7,173.92
UG_+1.2VSP on IN1 (solid shape): 178.46,174.49 178.46,172.77 178.34,172.65 177.7,172.65 177.57,172.77 177.57,174.42 177.77,174.61 178.34,174.61
UG_+1.2VSP on IN1 (solid shape): 184.75,173.79 184.75,173.03 183.8,172.07 183.54,172.07 183.26,172.36 183.26,172.93 184.18,173.85 184.69,173.85
UG_VGA_CORE on TOP (solid shape): 205.89,72.89 206.09,72.89 206.21,72.77 206.21,72.27 206.02,72.08 203.99,72.08 203.8,72.27 203.8,72.84 203.86,72.9 205.88,72.9
UG_VGA_CORE on TOP (solid shape): 206.15,65.08 206.15,64.63 205.96,64.44 203.8,64.44 203.55,64.7 203.55,65.34 203.67,65.47 205.75,65.47
UG_VGA_CORE on BOTTOM (solid shape): 203.93,62.85 203.93,62.16 204.18,61.9 204.24,61.9 204.31,61.84 204.31,60.89 204.24,60.82 204.12,60.82 204.05,60.89 204.05,61.08 203.1,62.03 203.1,62.73 203.36,62.98 203.8,62.98
UG_VGA_CORE on IN1 (solid shape): 204.94,72.51 204.94,71.87 204.69,71.62 202.85,71.62 202.47,71.24 202.47,67.5 204.63,65.34 204.63,65.09 203.86,64.33 203.86,62.03 203.74,61.9 203.17,61.9 202.78,62.28 202.78,65.08 201.39,66.47 201.39,72.12 201.96,72.7 204.75,72.7
VCIN1_PH on TOP (solid shape): 130.31,183.94 130.31,180.14 130.21,180.04 129.77,180.04 129.61,180.2 129.61,183.98 129.66,184.02 130.22,184.02
N16988653 on BOTTOM (solid shape): 215.65,94.45 215.65,92.88 216.07,92.46 217.77,92.46 218.02,92.22 218.02,91.05 217.85,90.88 215.03,90.88 213.58,92.33 213.58,92.84 213.64,92.9 214.09,92.9 214.15,92.97 214.15,94.3 214.09,94.36 213.71,94.36 213.58,94.49 213.58,95 213.71,95.13 214.98,95.13
N16988706 on BOTTOM (solid shape): 216.56,96.06 216.56,95.37 216.94,94.98 216.94,94.41 216.88,94.35 216.37,94.35 215.6,95.12 215.6,96.07 215.66,96.13 216.5,96.13
N17045846 on BOTTOM (solid shape): 202.85,64.12 202.85,63.3 202.72,63.17 200.94,63.17 200.88,63.23 200.88,63.81 200.94,63.87 201.64,63.87 201.96,64.19 202.78,64.19
N17046121 on BOTTOM (solid shape): 215.29,66.16 215.29,65.27 215.17,65.14 213.71,65.14 213.45,65.39 213.45,66.09 213.64,66.28 215.17,66.28
N17046121 on BOTTOM (solid shape): 215.55,72.25 215.55,71.3 215.48,71.24 215.04,71.24 214.85,71.05 213.58,71.05 213.45,71.17 213.45,71.62 213.61,71.78 214.5,71.78 215.07,72.35 215.45,72.35
N17046121 on BOTTOM (solid shape): 205.64,62.98 205.64,62.22 205.51,62.09 205.51,60.89 205.45,60.82 205.32,60.82 205.26,60.89 205.26,62.09 205.13,62.22 205.13,62.38 205.14,62.4 205.2,62.59 205.13,62.79 205.13,62.98 205.26,63.11 205.51,63.11
N17046121 on IN3 (solid shape): 215.55,72.12 215.55,71.36 215.48,71.3 214.91,71.3 214.72,71.11 214.72,66.41 214.85,66.28 215.17,66.28 215.36,66.09 215.36,65.33 215.23,65.2 212.25,65.2 212.18,65.27 212.18,66.03 212.44,66.28 213.33,66.28 213.45,66.41 213.45,71.93 213.77,72.25 215.42,72.25
N17046121 on IN3 (solid shape): 207.04,63.11 207.04,62.47 206.66,62.09 205.26,62.09 205.13,62.22 205.13,62.38 205.14,62.4 205.2,62.59 205.14,62.78 205.13,62.79 205.13,62.92 205.32,63.11 206.4,63.11 206.66,63.36 206.78,63.36
N17494823 on BOTTOM (solid shape): 28.54,27.88 28.54,27.18 27.91,26.55 27.91,25.72 27.71,25.53 27.52,25.53 27.27,25.28 27.27,24.39 27.08,24.2 26.51,24.2 26.44,24.26 26.44,25.53 27.02,26.1 27.02,27.54 26.9,27.65 26.26,27.65 26.14,27.77 26.14,28.02 26.23,28.11 28.31,28.11
N17608587 on BOTTOM (solid shape): 148.86,160.4 148.86,158.52 148.75,158.41 148.12,158.41 148.12,160.51 148.17,160.57 148.68,160.57
N18009264 on BOTTOM (solid shape): 148.05,166.93 148.05,163.37 147.54,162.87 142.71,162.87 142.65,162.93 142.65,163.69 142.78,163.82 144.3,163.82 144.55,164.07 144.55,164.45 144.43,164.58 142.71,164.58 142.59,164.71 142.59,165.28 142.65,165.34 144.75,165.34 145.38,165.98 145.38,166.8 145.7,167.12 147.86,167.12
N18009411 on BOTTOM (solid shape): 148.05,185.84 148.05,184.64 147.79,184.38 146.41,184.38 146.21,184.58 146.21,184.84 146.4,185.03 146.9,185.03 147.03,185.15 147.03,186.17 147.16,186.3 147.6,186.3
N18009417 on TOP (solid shape): 157.64,179.9 157.64,178.32 157.54,178.23 155.41,178.23 155.35,178.29 155.35,178.87 155.42,178.94 156.32,178.94 156.37,178.99 156.37,179.87 156.52,180.03 157.51,180.03
N18284053 on BOTTOM (solid shape): 138.15,178.67 138.15,176.14 137.91,175.9 135.94,175.9 135.41,175.37 135.41,172.14 137.95,169.6 137.95,167.57 137.81,167.42 135.33,167.42 135.03,167.72 135.03,167.91 133.03,169.91 133.03,176.36 135.63,178.96 137.87,178.96
N19792982 on BOTTOM (solid shape): 24.94,28.62 24.94,27.76 24.86,27.67 24.1,27.67 23.84,27.93 23.21,27.93 23.14,27.99 23.14,28.63 23.27,28.75 24.81,28.75
N21178712 on TOP (solid shape): 132.14,176.02 132.14,174.46 132.04,174.37 129.89,174.37 129.27,174.98 129.27,176.21 129.35,176.29 131.87,176.29
N32320781 on BOTTOM (solid shape): 140.81,167.35 140.81,166.42 141.7,165.53 141.7,164.64 141.63,164.58 140.11,164.58 139.86,164.33 139.86,164.01 140.11,163.76 141.57,163.76 141.7,163.63 141.7,163.18 141.44,162.93 138.71,162.93 138.27,163.37 138.27,166.93 138.71,167.37 140.78,167.37
N46608740 on BOTTOM (solid shape): 142.33,169.03 143.09,169.03 143.22,168.9 143.22,167.44 143.16,167.37 142.27,167.37 142.08,167.57 138.59,167.57 138.27,167.88 138.27,169.28 138.46,169.47 141.89,169.47
N46660696 on TOP (solid shape): 109.12,146.04 109.12,144.58 108.87,144.32 107.98,144.32 107.85,144.45 107.85,145.21 107.66,145.4 107.03,145.4 106.9,145.53 106.9,146.04 107.03,146.17 108.99,146.17
N47008006 on TOP (solid shape): 129.18,179.78 129.18,178.31 129.08,178.21 129.08,176.63 128.98,176.52 128.1,176.52 128,176.63 128,179.76 128.16,179.92 129.04,179.92
N47008301 on TOP (solid shape): 129.44,181.53 129.44,180.46 129.27,180.29 127.98,180.29 127.75,180.52 127.75,181.69 127.92,181.86 129.12,181.86
N47305899 on BOTTOM (solid shape): 214.72,64.68 214.72,63.03 213.71,63.03 212.94,63.79 212.69,63.79 212.63,63.86 212.63,64.68 212.69,64.75 214.66,64.75
N47415258 on BOTTOM (solid shape): 210.91,19.05 210.91,17.97 211.04,17.85 211.99,17.85 212.12,17.72 212.12,16.83 211.99,16.7 210.34,16.7 210.21,16.83 210.21,19.05 210.28,19.12 210.85,19.12
N47415272 on BOTTOM (solid shape): 212.31,23.88 212.25,23.82 211.23,23.82 210.79,23.37 210.79,22.61 210.72,22.55 210.21,22.55 210.09,22.67 210.09,24.32 210.66,24.89 212.31,24.89
N47417471 on BOTTOM (solid shape): 107.88,16.68 107.88,15.89 108.03,15.73 108.77,15.73 109.24,15.26 109.24,13.65 109.12,13.53 108.64,13.53 108.64,14.08 108.64,14.08 108.09,14.08 108.09,14.08 108.09,13.53 108.09,13.53 107.84,13.53 107.84,13.53 107.84,14.08 107.84,14.09 107.29,14.09 107.28,14.08 107.28,13.56 107.26,13.53 106.95,13.53 106.24,14.24 104.27,14.24 104.15,14.37 104.15,15.53 104.35,15.73 107.49,15.73 107.62,15.86 107.62,16.68 107.68,16.74 107.81,16.74
N47417524 on BOTTOM (solid shape): 105.16,19.55 105.16,18.72 105.6,18.29 105.6,17.76 105.56,17.72 105.03,17.72 104.48,18.27 104.48,19.51 104.55,19.58 105.13,19.58
N47420895 on BOTTOM (solid shape): 161.83,13.51 161.83,11.93 161.76,11.86 160.62,11.86 159.73,12.75 157.06,12.75 156.94,12.88 156.94,13.39 157.06,13.51 160.62,13.51 160.68,13.58 161.76,13.58
N64564173 on TOP (solid shape): 183.61,172.58 183.61,172.01 184.05,171.57 184.05,170.74 183.99,170.68 183.35,170.68 183.23,170.8 183.23,171.38 182.72,171.88 182.72,172.58 182.78,172.65 183.54,172.65
N64564191 on TOP (solid shape): 180.75,173.34 180.75,172.71 181,172.45 181.7,172.45 181.83,172.33 181.83,171.63 181.7,171.5 179.8,171.5 179.67,171.63 179.67,173.28 179.8,173.41 180.69,173.41

Small or netless copper shapes (teardrops, artwork), in the pictures only: 19 on TOP, 362 on BOTTOM

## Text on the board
Ref Des/Silkscreen Bottom: H10 | H7 | H6 | H19 | H20 | SODIMM-only support DDR3L
User.Comments: LA9984P | Kerry | 2013-05-22 | 2014-05-22 | VBW11 | 1.0(A00)
COMPVAL_TYPE_BOTTOM: trace Width | Width/space | 6.5mil | 7.2mil | 8.2mil | 6.2mil | 5mil | 4mil | 4.3 / 4 | 5.5 / 4.5 | 5 / 4.9 | 5 / 4.5 | 4 / 4.5 | 5 / 5 | 5 / 5.7 | 4 / 6.5 | 4.5/5.5 | 5 / 8 | 4 / 12 | L1-TOP | L2-GND1 | L3-IN1 | L4-VCC | L5-IN2 | L6-IN3 | L7-GND2 | L8-BOT | LAYER | NAME | SB_1_2mm-6L and 8L and 10L(4mil & 5mil 50ohm)_120807 | STACKUP: 8 LAYER | 39 ohm | 45 ohm | THICKNESS=1.2mm | 50 ohm | 80 ohm | 83 ohm | 85 ohm | 90 ohm | 100 ohm
